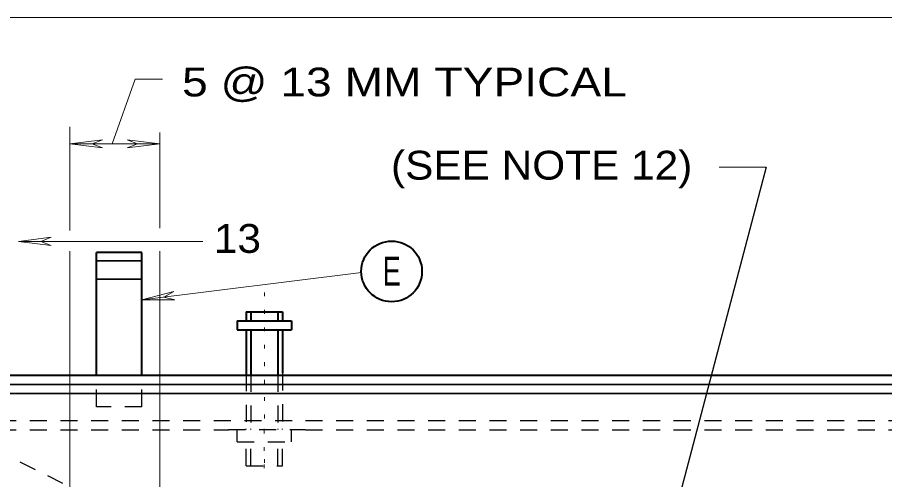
# Model space of a CAD drawing. Extents: x 312583 to 312854, y 144419 to 144597.
# Drawn here: x 312691.31 to 312714.2, y 144559.81 to 144572.01 of the extents above; entities that cross this region are included whole.
import ezdxf

# ---------------------------------------------------------------- set-up
doc = ezdxf.new("R2010")
doc.units = 0
doc.header["$LTSCALE"] = 0.3
doc.linetypes.add('DOTTED', pattern=[1.5, 0.3, -1.2])
doc.linetypes.add('SHORT_DASHED', pattern=[2.7, 1.5, -1.2])
doc.layers.add('1', color=7, linetype='Continuous', lineweight=40)
doc.layers.add('2', color=7, linetype='Continuous', lineweight=13)

msp = doc.modelspace()

# ---------------------------------------------------------------- linework, layer by layer
at = {"layer": '1', "lineweight": 25}
msp.add_line((312711.0702, 144568.0539), (312707.4055, 144554.1466), dxfattribs=at)
at = {"layer": '1'}
for p, q in [((312694.5945, 144565.8076), (312693.3985, 144565.8076)), ((312693.3985, 144562.5799), (312693.3985, 144565.8076)), ((312694.5945, 144562.5799), (312694.5945, 144565.8076)), ((312697.3469, 144564.2436), (312698.3052, 144564.2436)), ((312697.3469, 144564.2436), (312697.3469, 144564.0059)), ((312697.4695, 144564.2436), (312697.4695, 144564.0059)), ((312698.1825, 144564.2436), (312698.1825, 144564.0059)), ((312698.3052, 144564.2436), (312698.3052, 144564.0059)), ((312697.1092, 144564.0059), (312698.5429, 144564.0059)), ((312697.1092, 144564.0059), (312697.1092, 144563.7683)), ((312698.5429, 144564.0059), (312698.5429, 144563.7683)), ((312697.1092, 144563.7683), (312698.5429, 144563.7683)), ((312697.3469, 144563.7683), (312697.3469, 144562.5953)), ((312697.4695, 144563.7683), (312697.4695, 144562.5799)), ((312698.1825, 144563.7683), (312698.1825, 144562.5799)), ((312698.3052, 144563.7683), (312698.3052, 144562.6183))]:
    msp.add_line(p, q, dxfattribs=at)
at = {"layer": '1', "lineweight": 35}
for p, q in [((312693.3985, 144565.5853), (312694.5945, 144565.5853)), ((312693.3985, 144565.1023), (312694.5945, 144565.1023)), ((312688.4842, 144562.0893), (312724.4179, 144562.0893))]:
    msp.add_line(p, q, dxfattribs=at)
at = {"layer": '1', "linetype": 'DOTTED', "lineweight": 13}
for p, q in [((312697.8299, 144564.7496), (312697.8299, 144561.3839)), ((312697.8222, 144561.1539), (312697.8222, 144561.1386)), ((312697.8222, 144561.1309), (312697.8222, 144560.1189)), ((312697.8299, 144560.3566), (312697.8299, 144559.9273))]:
    msp.add_line(p, q, dxfattribs=at)
at = {"layer": '1', "linetype": 'SHORT_DASHED', "lineweight": 25}
for p, q in [((312693.3985, 144561.7366), (312693.3985, 144562.5799)), ((312694.5945, 144561.7366), (312694.5945, 144562.5799)), ((312697.3469, 144562.5953), (312697.3469, 144561.1386)), ((312697.4695, 144562.5799), (312697.4695, 144561.1386)), ((312698.1825, 144562.5799), (312698.1825, 144561.1386)), ((312698.3052, 144562.6106), (312698.3052, 144561.1386)), ((312694.5945, 144561.7366), (312693.3985, 144561.7366)), ((312689.2049, 144561.3686), (312723.7049, 144544.1186)), ((312689.2049, 144561.1309), (312696.8869, 144561.1309)), ((312696.8792, 144561.1386), (312698.9032, 144561.1386)), ((312697.1092, 144560.8089), (312697.1092, 144561.1233)), ((312697.3392, 144561.1539), (312697.3392, 144561.1386)), ((312697.4619, 144561.1539), (312697.4619, 144561.1386)), ((312698.1825, 144561.1539), (312698.1825, 144561.1386)), ((312698.2975, 144561.1539), (312698.2975, 144561.1386)), ((312698.5429, 144560.8089), (312698.5429, 144561.1309)), ((312698.9109, 144561.1309), (312723.7049, 144561.1309)), ((312697.1092, 144560.8089), (312698.5429, 144560.8089)), ((312697.3469, 144560.1726), (312697.3469, 144560.8089)), ((312697.4695, 144560.1726), (312697.4695, 144560.8089)), ((312698.1825, 144560.1726), (312698.1825, 144560.8089)), ((312698.3052, 144560.1726), (312698.3052, 144560.8089)), ((312697.3469, 144560.1726), (312698.3052, 144560.1726))]:
    msp.add_line(p, q, dxfattribs=at)
at = {"layer": '1'}
msp.add_lwpolyline([(312688.0012, 144562.5723), (312724.9009, 144562.5723), (312724.9009, 144542.9226)], dxfattribs=at)
at = {"layer": '1', "lineweight": 35}
msp.add_lwpolyline([(312688.2465, 144562.3269), (312724.6632, 144562.3269), (312724.6632, 144543.1603)], dxfattribs=at)
at = {"layer": '1', "linetype": 'SHORT_DASHED', "lineweight": 25}
msp.add_lwpolyline([(312689.2049, 144561.3686), (312698.9109, 144561.3686), (312723.7049, 144561.3686)], dxfattribs=at)
at = {"layer": '2'}
for p, q in [((312688.4535, 144572.0099), (312724.4715, 144572.0099)), ((312692.6932, 144566.3903), (312692.6932, 144569.1196)), ((312695.0699, 144566.4439), (312695.0699, 144568.9739)), ((312692.6932, 144568.6749), (312693.5595, 144568.7823)), ((312692.6932, 144568.6749), (312695.0699, 144568.6749)), ((312692.6932, 144568.6749), (312693.5595, 144568.5676)), ((312693.5595, 144568.7823), (312693.2835, 144568.6749)), ((312693.5595, 144568.5676), (312693.2835, 144568.6749)), ((312694.2035, 144568.7823), (312694.4795, 144568.6749)), ((312695.0699, 144568.6749), (312694.2035, 144568.7823)), ((312694.2035, 144568.5676), (312694.4795, 144568.6749)), ((312695.0699, 144568.6749), (312694.2035, 144568.5676)), ((312709.8282, 144568.0539), (312711.0702, 144568.0539)), ((312691.3362, 144566.0989), (312692.2025, 144566.2063)), ((312692.2025, 144566.2063), (312691.9265, 144566.0989)), ((312691.3362, 144566.0989), (312696.2045, 144566.0989)), ((312691.3362, 144566.0989), (312692.2025, 144565.9916)), ((312692.2025, 144565.9916), (312691.9265, 144566.0989)), ((312692.6932, 144559.4289), (312692.6932, 144565.8383)), ((312695.0699, 144559.2373), (312695.0699, 144565.8383)), ((312700.3905, 144565.2786), (312694.5945, 144564.5579)), ((312694.5945, 144564.5579), (312695.4379, 144564.7726)), ((312695.4379, 144564.7726), (312695.1772, 144564.6269)), ((312694.5945, 144564.5579), (312695.4685, 144564.5579)), ((312695.4685, 144564.5579), (312695.1772, 144564.6269))]:
    msp.add_line(p, q, dxfattribs=at)
msp.add_lwpolyline([(312695.1389, 144570.3769), (312694.4182, 144570.3769), (312693.8125, 144568.6749)], dxfattribs=at)
at = {"layer": '2', "lineweight": 40}
msp.add_circle((312701.1879, 144565.3064), 0.8012, dxfattribs=at)

# ---------------------------------------------------------------- texts
at = {"layer": '2'}
for s, width, p in [('5 @ 13 MM TYPICAL', 1.2, (312695.6562, 144569.9235)), ('(SEE NOTE 12)', 1.1, (312701.1715, 144567.729)), ('13 ', 1.1, (312696.4969, 144565.796)), ('E', 0.7, (312700.9521, 144564.9336))]:
    msp.add_text(s, height=0.76, dxfattribs=dict(at, width=width)).set_placement(p)

doc.saveas('drawing.dxf')
